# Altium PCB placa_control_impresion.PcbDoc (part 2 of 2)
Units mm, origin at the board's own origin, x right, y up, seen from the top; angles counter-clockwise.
Board outline 71.3 x 86.83 mm, 2 copper layers (Top Layer, Bottom Layer); 160 components, 36 nets, 619 pads, 364 vias.
Unrouted connection lines stored in the file: 1.
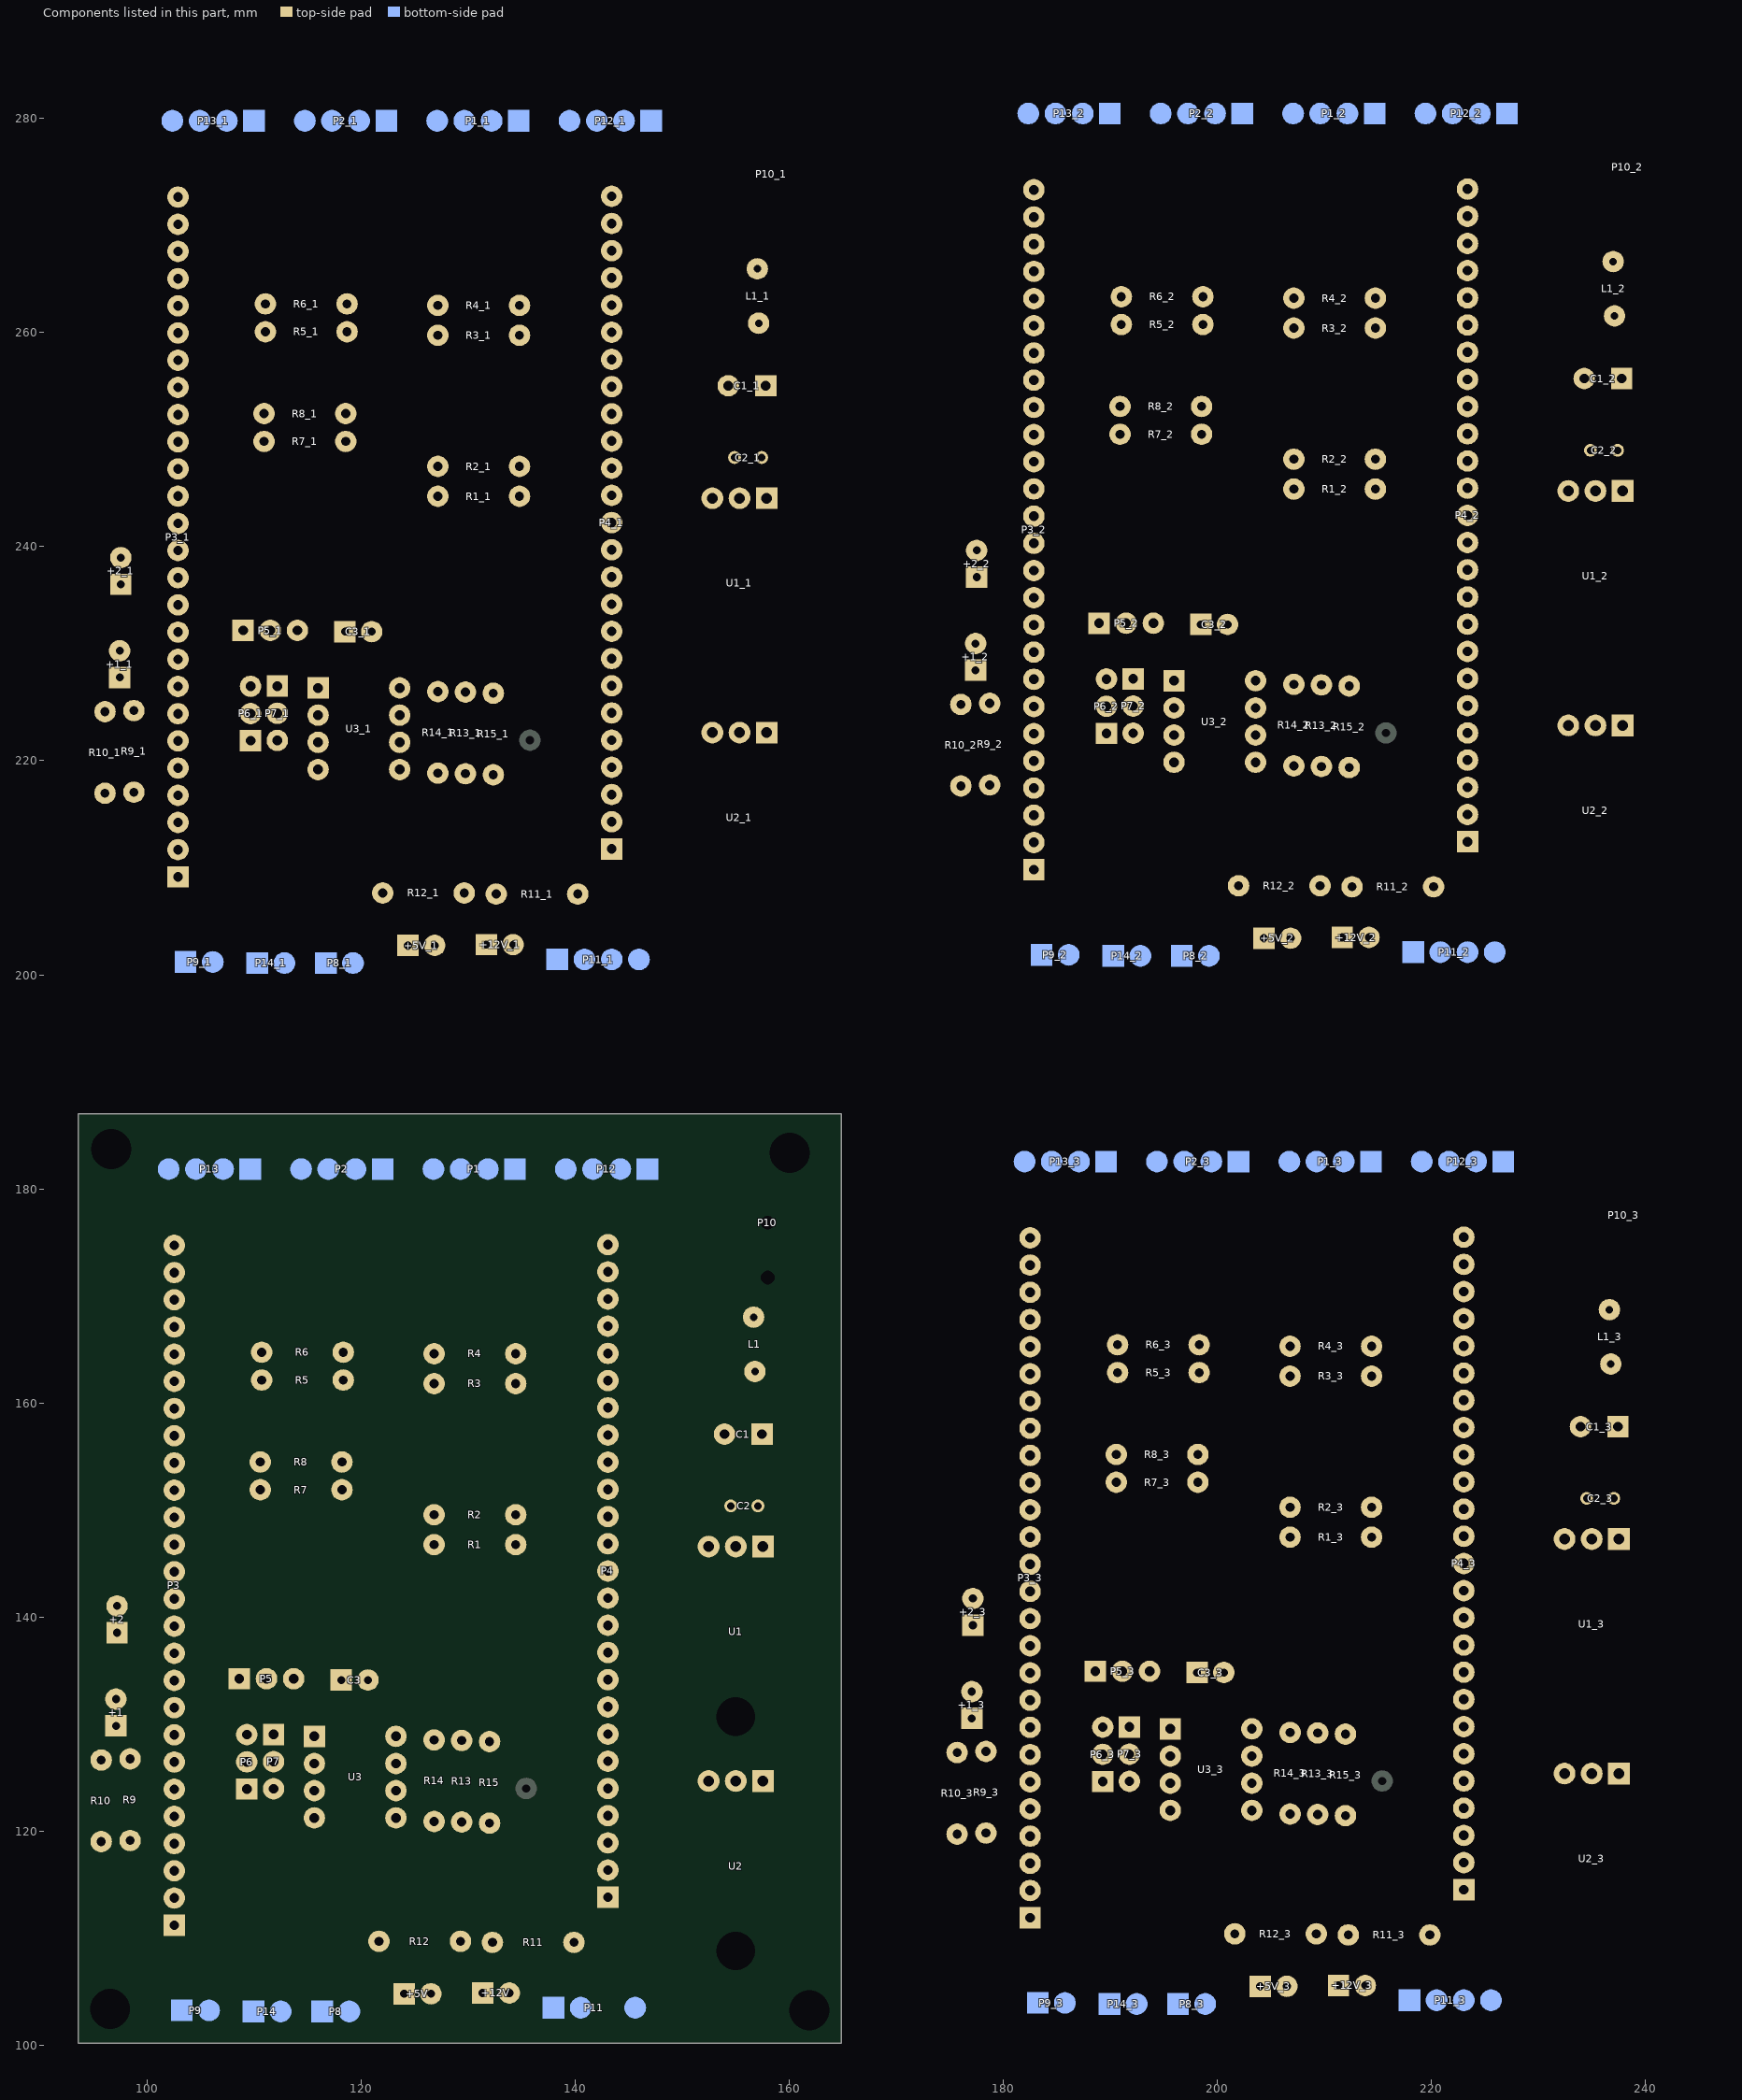
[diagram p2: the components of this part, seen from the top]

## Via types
v1: diameter 2, hole 0.711, Top Layer to Bottom Layer, 364 vias

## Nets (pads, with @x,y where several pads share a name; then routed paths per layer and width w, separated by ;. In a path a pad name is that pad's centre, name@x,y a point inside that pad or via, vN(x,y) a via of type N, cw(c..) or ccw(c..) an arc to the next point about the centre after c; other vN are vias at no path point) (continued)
pads on no net: +1_1.1 +1_1.2 +1_2.1 +1_2.2 +1_3.1 +1_3.2 +2_1.1 +2_1.2 +2_2.1 +2_2.2 +2_3.1 +2_3.2 +5V_1.1 +5V_1.2 +5V_2.1 +5V_2.2 +5V_3.1 +5V_3.2 +12V_1.1 +12V_1.2 +12V_2.1 +12V_2.2 +12V_3.1 +12V_3.2 C1_1.1 C1_1.2 C1_2.1 C1_2.2 C1_3.1 C1_3.2 C2_1.1 C2_1.2 C2_2.1 C2_2.2 C2_3.1 C2_3.2 C3_1.1 C3_1.2 C3_2.1 C3_2.2 C3_3.1 C3_3.2 L1_1.1 L1_1.2 L1_2.1 L1_2.2 L1_3.1 L1_3.2 P1_1.1 P1_1.2 P1_1.3 P1_1.4 P1_2.1 P1_2.2 P1_2.3 P1_2.4 P1_3.1 P1_3.2 P1_3.3 P1_3.4 P2_1.1 P2_1.2 P2_1.3 P2_1.4 P2_2.1 P2_2.2 P2_2.3 P2_2.4 P2_3.1 P2_3.2 P2_3.3 P2_3.4 P3.1 P3.3 P3.4 P3.5 P3.12 P3.13 P3.18 P3.19 P3.22 P3.23 P3.24 P3.25 P3.26 P3_1.1 P3_1.2 P3_1.3 P3_1.4 P3_1.5 P3_1.6 P3_1.7 P3_1.8 P3_1.9 P3_1.10 P3_1.11 P3_1.12 P3_1.13 P3_1.14 P3_1.15 P3_1.16 P3_1.17 P3_1.18 P3_1.19 P3_1.20 P3_1.21 P3_1.22 P3_1.23 P3_1.24 P3_1.25 P3_1.26 P3_2.1 P3_2.2 P3_2.3 P3_2.4 P3_2.5 P3_2.6 P3_2.7 P3_2.8 P3_2.9 P3_2.10 P3_2.11 P3_2.12 P3_2.13 P3_2.14 P3_2.15 P3_2.16 P3_2.17 P3_2.18 P3_2.19 P3_2.20 P3_2.21 P3_2.22 P3_2.23 P3_2.24 P3_2.25 P3_2.26 P3_3.1 P3_3.2 P3_3.3 P3_3.4 P3_3.5 P3_3.6 P3_3.7 P3_3.8 P3_3.9 P3_3.10 P3_3.11 P3_3.12 P3_3.13 P3_3.14 P3_3.15 P3_3.16 P3_3.17 P3_3.18 P3_3.19 P3_3.20 P3_3.21 P3_3.22 P3_3.23 P3_3.24 P3_3.25 P3_3.26 P4.3 P4.4 P4.6 P4.7 P4.8 P4.9 P4.10 P4.11 P4.12 P4.13 P4.17 P4.18 P4.19 P4.20 P4.22 P4.23 P4.24 P4.25 P4_1.1 P4_1.2 P4_1.3 P4_1.4 P4_1.5 P4_1.6 P4_1.7 P4_1.8 P4_1.9 P4_1.10 P4_1.11 P4_1.12 P4_1.13 P4_1.14 P4_1.15 P4_1.16 P4_1.17 P4_1.18 P4_1.19 P4_1.20 P4_1.21 P4_1.22 P4_1.23 P4_1.24 P4_1.25 P4_2.1 P4_2.2 P4_2.3 P4_2.4 P4_2.5 P4_2.6 P4_2.7 P4_2.8 P4_2.9 P4_2.10 P4_2.11 P4_2.12 P4_2.13 P4_2.14 P4_2.15 P4_2.16 P4_2.17 P4_2.18 P4_2.19 P4_2.20 P4_2.21 P4_2.22 P4_2.23 P4_2.24 P4_2.25 P4_3.1 P4_3.2 P4_3.3 P4_3.4 P4_3.5 P4_3.6 P4_3.7 P4_3.8 P4_3.9 P4_3.10 P4_3.11 P4_3.12 P4_3.13 P4_3.14 P4_3.15 P4_3.16 P4_3.17 P4_3.18 P4_3.19 P4_3.20 P4_3.21 P4_3.22 P4_3.23 P4_3.24 P4_3.25 P5_1.1 P5_1.2 P5_1.3 P5_2.1 P5_2.2 P5_2.3 P5_3.1 P5_3.2 P5_3.3 P6_1.1 P6_1.2 P6_1.3 P6_2.1 P6_2.2 P6_2.3 P6_3.1 P6_3.2 P6_3.3 P7_1.1 P7_1.2 P7_1.3 P7_2.1 P7_2.2 P7_2.3 P7_3.1 P7_3.2 P7_3.3 P8_1.1 P8_1.2 P8_2.1 P8_2.2 P8_3.1 P8_3.2 P9_1.1 P9_1.2 P9_2.1 P9_2.2 P9_3.1 P9_3.2 P10_1.2 P10_2.2 P10_3.2 P11_1.1 P11_1.2 P11_1.3 P11_1.4 P11_2.1 P11_2.2 P11_2.3 P11_2.4 P11_3.1 P11_3.2 P11_3.3 P11_3.4 P12_1.1 P12_1.2 P12_1.3 P12_1.4 P12_2.1 P12_2.2 P12_2.3 P12_2.4 P12_3.1 P12_3.2 P12_3.3 P12_3.4 P13_1.1 P13_1.2 P13_1.3 P13_1.4 P13_2.1 P13_2.2 P13_2.3 P13_2.4 P13_3.1 P13_3.2 P13_3.3 P13_3.4 P14_1.1 P14_1.2 P14_2.1 P14_2.2 P14_3.1 P14_3.2 R1_1.1 R1_1.2 R1_2.1 R1_2.2 R1_3.1 R1_3.2 R2_1.1 R2_1.2 R2_2.1 R2_2.2 R2_3.1 R2_3.2 R3_1.1 R3_1.2 R3_2.1 R3_2.2 R3_3.1 R3_3.2 R4_1.1 R4_1.2 R4_2.1 R4_2.2 R4_3.1 R4_3.2 R5_1.1 R5_1.2 R5_2.1 R5_2.2 R5_3.1 R5_3.2 R6_1.1 R6_1.2 R6_2.1 R6_2.2 R6_3.1 R6_3.2 R7_1.1 R7_1.2 R7_2.1 R7_2.2 R7_3.1 R7_3.2 R8_1.1 R8_1.2 R8_2.1 R8_2.2 R8_3.1 R8_3.2 R9_1.1 R9_1.2 R9_2.1 R9_2.2 R9_3.1 R9_3.2 R10_1.1 R10_1.2 R10_2.1 R10_2.2 R10_3.1 R10_3.2 R11_1.1 R11_1.2 R11_2.1 R11_2.2 R11_3.1 R11_3.2 R12_1.1 R12_1.2 R12_2.1 R12_2.2 R12_3.1 R12_3.2 R13_1.1 R13_1.2 R13_2.1 R13_2.2 R13_3.1 R13_3.2 R14_1.1 R14_1.2 R14_2.1 R14_2.2 R14_3.1 R14_3.2 R15_1.1 R15_1.2 R15_2.1 R15_2.2 R15_3.1 R15_3.2 U1_1.1 U1_1.2 U1_1.3 U1_1.4 U1_2.1 U1_2.2 U1_2.3 U1_2.4 U1_3.1 U1_3.2 U1_3.3 U1_3.4 U2_1.1 U2_1.2 U2_1.3 U2_1.4 U2_2.1 U2_2.2 U2_2.3 U2_2.4 U2_3.1 U2_3.2 U2_3.3 U2_3.4 U3_1.1 U3_1.2 U3_1.3 U3_1.4 U3_1.5 U3_1.6 U3_1.7 U3_1.8 U3_2.1 U3_2.2 U3_2.3 U3_2.4 U3_2.5 U3_2.6 U3_2.7 U3_2.8 U3_3.1 U3_3.2 U3_3.3 U3_3.4 U3_3.5 U3_3.6 U3_3.7 U3_3.8
copper on no net: | length 3961
  Bottom Layer w0.8: 95.975,224.55 95.975,225.1 95.55,225.525 95.55,231.425 97.55,233.425 97.55,236.475 ; 96.075,216.965 96.075,209.15 98.939,206.286 98.989,206.286 101.525,203.75 101.525,199.7 102.5,198.725 113.475,198.725 114.725,199.975 ; 97.25,238.975 98.225,238.975 102.575,234.625 ; 97.45,227.775 98.475,227.775 98.775,227.475 98.775,224.685 ; 97.45,230.275 97.45,230.525 99.01,232.085 v1@106.45,232.085 ; v1@98.9,164.64 v1@106.215,164.64 ; v1@98.94,116.38 v1@106.125,116.38 ; v1@98.94,154.48 v1@106.125,154.48 ; v1@98.94,157.02 v1@106.125,157.02 ; v1@98.94,167.18 v1@106.125,167.18 ; v1@98.94,169.72 v1@106.125,169.72 ; v1@98.94,172.26 v1@106.125,172.26 ; v1@98.94,174.8 v1@106.125,174.8 ; v1@99.01,111.23 v1@106.195,111.23 ; v1@99.15,260.025 111.055,260.025 111.065,260.015 111.065,262.675 ; v1@99.25,262.565 v1@106.565,262.565 ; v1@99.29,211.765 v1@106.475,211.765 ; v1@99.29,214.305 v1@106.475,214.305 ; v1(99.29,242.245) 107.355,242.245 108.975,240.625 108.975,232.175 ; v1(99.29,244.785) 107.74,244.785 111.515,241.01 111.515,232.175 ; v1(99.29,247.325) v1(106.475,247.325) ; v1@99.29,249.865 v1@106.475,249.865 ; v1@99.29,252.405 v1@106.475,252.405 ; v1@99.29,254.945 v1@106.475,254.945 ; v1@99.29,257.485 v1@106.475,257.485 ; v1@99.29,265.105 v1@106.475,265.105 ; v1@99.29,267.645 v1@106.475,267.645 ; v1@99.29,270.185 v1@106.475,270.185 ; v1@99.29,272.725 v1@106.475,272.725 ; v1@99.36,209.155 v1@106.545,209.155 ; 102.325,121.46 v1@106.125,121.46 ; 102.35,118.92 v1@106.125,118.92 ; 102.375,139.24 v1@106.125,139.24 ; 102.425,141.78 v1@106.125,141.78 ; 102.55,224.415 108.675,224.415 ; 102.675,219.385 v1@106.475,219.385 ; 102.7,216.845 v1@106.475,216.845 ; 102.725,237.165 v1@106.475,237.165 ; 102.775,239.705 v1@106.475,239.705 ; 102.8,221.925 109.625,221.925 109.675,221.875 ; 102.825,226.955 109.675,226.955 ; 102.825,229.545 108.02,229.545 108.85,230.375 114.85,230.375 116.025,231.55 116.025,245.325 114.45,246.9 114.45,270.05 109.995,274.505 109.995,279.78 ; 102.85,234.625 v1@106.475,234.625 ; 103.605,201.2 103.605,202.705 108.225,207.325 108.225,207.375 108.85,208 108.85,210.925 107.985,211.79 v1(106.45,211.79) ; 104.145,201.15 104.25,201.255 ; v1(106.45,249.89) 110.835,249.89 111,249.725 ; v1(106.45,257.51) 111.185,257.51 113.25,259.575 113.25,269.55 107.455,275.345 107.455,279.78 ; v1@106.5,247.425 109.1,247.425 114.055,242.47 114.055,232.175 ; 109.625,224.465 109.675,224.415 ; 110.94,249.825 110.94,252.425 ; 114.725,200 114.725,205.232 122.443,212.95 129.3,212.95 134.25,217.9 134.25,220.325 133.7,220.875 133.7,223.943 ; 114.742,279.78 114.742,274.358 115.65,273.45 115.65,251.175 117,249.825 118.56,249.825 ; 115.984,219.18 117.155,219.18 117.537,219.562 ; 115.984,221.72 116.06,221.795 116.06,224.29 116.1,224.25 ; 116.705,201.1 116.705,205.055 122.475,210.825 129.1,210.825 135.85,217.575 135.85,220.775 135.775,221.925 ; 117.282,279.78 117.282,274.359 116.85,273.927 116.85,261.91 118.685,260.075 ; 122.015,207.65 122.3,207.65 124.375,205.575 124.375,202.75 ; 127.075,279.025 127.075,270 129.075,268 129.075,261.2 127.618,259.743 127.174,259.743 ; 127.174,244.702 130.275,247.803 130.275,268.55 129.775,269.05 129.775,279.75 ; 131.725,203.025 131.725,207.49 ; 132.615,207.55 133.05,207.115 ; 134.644,260.325 134.669,260.35 ; 134.644,262.5 134.694,262.55 v1(139.6,262.55) ; 134.669,262.5 134.669,262.525 ; 134.725,244.8 134.755,244.77 v1(139.6,244.77) v1@139.532,244.702 ; 134.794,259.743 134.794,262.535 ; 134.825,244.825 134.825,247.675 ; v1@139.555,118.92 v1@146.74,118.92 ; v1@139.555,121.46 v1@146.74,121.46 ; v1@139.555,126.54 v1@146.74,126.54 ; v1@139.555,129.08 v1@146.74,129.08 ; v1@139.555,131.62 v1@146.74,131.62 ; v1@139.555,134.16 v1@146.74,134.16 ; v1@139.555,136.7 v1@146.74,136.7 ; v1@139.555,139.24 v1@146.74,139.24 ; v1@139.555,141.78 v1@146.74,141.78 ; v1@139.555,144.32 v1@146.74,144.32 ; v1@139.555,154.48 v1@146.74,154.48 ; v1@139.555,157.02 v1@146.74,157.02 ; v1@139.555,159.56 v1@146.74,159.56 ; v1@139.555,162.1 v1@146.74,162.1 ; v1@139.555,167.18 v1@146.74,167.18 ; v1@139.555,169.72 v1@146.74,169.72 ; v1@139.555,172.26 v1@146.74,172.26 ; v1@139.555,174.8 v1@146.74,174.8 ; v1(139.6,247.31) 137.64,247.31 136.41,248.54 136.41,253.39 132.75,257.05 132.75,270.5 137.7,275.45 143.075,275.45 144.555,276.93 144.555,279.78 ; v1@139.905,211.765 v1@147.09,211.765 ; v1@139.905,216.845 v1@147.09,216.845 ; v1@139.905,219.385 v1@147.09,219.385 ; v1@139.905,221.925 v1@147.09,221.925 ; v1@139.905,224.465 v1@147.09,224.465 ; v1@139.905,227.005 v1@147.09,227.005 ; v1@139.905,229.545 v1@147.09,229.545 ; v1@139.905,232.085 v1@147.09,232.085 ; v1@139.905,234.625 v1@147.09,234.625 ; v1@139.905,237.165 v1@147.09,237.165 ; v1@139.905,239.705 v1@147.09,239.705 ; v1@139.905,242.245 v1@147.09,242.245 ; v1@139.905,244.785 v1@147.09,244.785 ; v1@139.905,247.325 v1@147.09,247.325 ; v1@139.905,249.865 147.665,249.865 149.025,251.225 149.025,274.825 147.095,276.755 147.095,279.78 ; v1@139.905,252.405 v1@147.09,252.405 ; v1@139.905,254.945 v1@147.09,254.945 ; v1@139.905,257.485 v1@147.09,257.485 ; v1@139.905,260.025 v1@147.09,260.025 ; v1@139.905,262.565 v1@147.09,262.565 ; v1@139.905,265.105 v1@147.09,265.105 ; v1@139.905,267.645 v1@147.09,267.645 ; v1@139.905,270.185 v1@147.09,270.185 ; v1@139.905,272.725 v1@147.09,272.725 ; 140.235,207.55 136.3,203.615 136.3,200.125 137.55,198.875 144.775,198.875 145.95,200.05 145.95,201.445 ; 175.575,127.325 175.575,127.875 175.15,128.3 175.15,134.2 177.15,136.2 177.15,139.25 ; 175.675,119.74 175.675,111.925 178.539,109.061 178.589,109.061 181.125,106.525 181.125,102.475 182.1,101.5 193.075,101.5 194.325,102.75 ; 175.925,225.225 175.925,225.775 175.5,226.2 175.5,232.1 177.5,234.1 177.5,237.15 ; 176.025,217.64 176.025,209.825 178.889,206.961 178.939,206.961 181.475,204.425 181.475,200.375 182.45,199.4 193.425,199.4 194.675,200.65 ; 176.85,141.75 177.825,141.75 182.175,137.4 ; 177.05,130.55 178.075,130.55 178.375,130.25 178.375,127.46 ; 177.05,133.05 177.05,133.3 178.61,134.86 v1@186.05,134.86 ; 177.2,239.65 178.175,239.65 182.525,235.3 ; 177.4,228.45 178.425,228.45 178.725,228.15 178.725,225.36 ; 177.4,230.95 177.4,231.2 178.96,232.76 v1@186.4,232.76 ; v1@178.75,162.8 190.655,162.8 190.665,162.79 190.665,165.45 ; v1@178.85,165.34 v1@186.165,165.34 ; v1@178.89,114.54 v1@186.075,114.54 ; v1@178.89,117.08 v1@186.075,117.08 ; v1(178.89,145.02) 186.955,145.02 188.575,143.4 188.575,134.95 ; v1(178.89,147.56) 187.34,147.56 191.115,143.785 191.115,134.95 ; v1(178.89,150.1) v1(186.075,150.1) ; v1@178.89,152.64 v1@186.075,152.64 ; v1@178.89,155.18 v1@186.075,155.18 ; v1@178.89,157.72 v1@186.075,157.72 ; v1@178.89,160.26 v1@186.075,160.26 ; v1@178.89,167.88 v1@186.075,167.88 ; v1@178.89,170.42 v1@186.075,170.42 ; v1@178.89,172.96 v1@186.075,172.96 ; v1@178.89,175.5 v1@186.075,175.5 ; v1@178.96,111.93 v1@186.145,111.93 ; v1@179.1,260.7 191.005,260.7 191.015,260.69 191.015,263.35 ; v1@179.2,263.24 v1@186.515,263.24 ; v1@179.24,212.44 v1@186.425,212.44 ; v1@179.24,214.98 v1@186.425,214.98 ; v1(179.24,242.92) 187.305,242.92 188.925,241.3 188.925,232.85 ; v1(179.24,245.46) 187.69,245.46 191.465,241.685 191.465,232.85 ; v1(179.24,248) v1(186.425,248) ; v1@179.24,250.54 v1@186.425,250.54 ; v1@179.24,253.08 v1@186.425,253.08 ; v1@179.24,255.62 v1@186.425,255.62 ; v1@179.24,258.16 v1@186.425,258.16 ; v1@179.24,265.78 v1@186.425,265.78 ; v1@179.24,268.32 v1@186.425,268.32 ; v1@179.24,270.86 v1@186.425,270.86 ; v1@179.24,273.4 v1@186.425,273.4 ; v1@179.31,209.83 v1@186.495,209.83 ; 182.15,127.19 188.275,127.19 ; 182.275,122.16 v1@186.075,122.16 ; 182.3,119.62 v1@186.075,119.62 ; 182.325,139.94 v1@186.075,139.94 ; 182.375,142.48 v1@186.075,142.48 ; 182.4,124.7 189.225,124.7 189.275,124.65 ; 182.425,129.73 189.275,129.73 ; 182.425,132.32 187.62,132.32 188.45,133.15 194.45,133.15 195.625,134.325 195.625,148.1 194.05,149.675 194.05,172.825 189.595,177.28 189.595,182.555 ; 182.45,137.4 v1@186.075,137.4 ; 182.5,225.09 188.625,225.09 ; 182.625,220.06 v1@186.425,220.06 ; 182.65,217.52 v1@186.425,217.52 ; 182.675,237.84 v1@186.425,237.84 ; 182.725,240.38 v1@186.425,240.38 ; 182.75,222.6 189.575,222.6 189.625,222.55 ; 182.775,227.63 189.625,227.63 ; 182.775,230.22 187.97,230.22 188.8,231.05 194.8,231.05 195.975,232.225 195.975,246 194.4,247.575 194.4,270.725 189.945,275.18 189.945,280.455 ; 182.8,235.3 v1@186.425,235.3 ; 183.205,103.975 183.205,105.48 187.825,110.1 187.825,110.15 188.45,110.775 188.45,113.7 187.585,114.565 v1(186.05,114.565) ; 183.555,201.875 183.555,203.38 188.175,208 188.175,208.05 188.8,208.675 188.8,211.6 187.935,212.465 v1(186.4,212.465) ; 183.745,103.925 183.85,104.03 ; 184.095,201.825 184.2,201.93 ; v1(186.05,152.665) 190.435,152.665 190.6,152.5 ; v1(186.05,160.285) 190.785,160.285 192.85,162.35 192.85,172.325 187.055,178.12 187.055,182.555 ; v1@186.1,150.2 188.7,150.2 193.655,145.245 193.655,134.95 ; v1(186.4,250.565) 190.785,250.565 190.95,250.4 ; v1(186.4,258.185) 191.135,258.185 193.2,260.25 193.2,270.225 187.405,276.02 187.405,280.455 ; v1@186.45,248.1 189.05,248.1 194.005,243.145 194.005,232.85 ; 189.225,127.24 189.275,127.19 ; 189.575,225.14 189.625,225.09 ; 190.54,152.6 190.54,155.2 ; 190.89,250.5 190.89,253.1 ; 194.325,102.775 194.325,108.007 202.043,115.725 208.9,115.725 213.85,120.675 213.85,123.1 213.3,123.65 213.3,126.718 ; 194.342,182.555 194.342,177.133 195.25,176.225 195.25,153.95 196.6,152.6 198.16,152.6 ; 194.675,200.675 194.675,205.907 202.393,213.625 209.25,213.625 214.2,218.575 214.2,221 213.65,221.55 213.65,224.618 ; 194.692,280.455 194.692,275.033 195.6,274.125 195.6,251.85 196.95,250.5 198.51,250.5 ; 195.584,121.955 196.755,121.955 197.137,122.337 ; 195.584,124.495 195.66,124.57 195.66,127.065 195.7,127.025 ; 195.934,219.855 197.105,219.855 197.487,220.237 ; 195.934,222.395 196.01,222.47 196.01,224.965 196.05,224.925 ; 196.305,103.875 196.305,107.83 202.075,113.6 208.7,113.6 215.45,120.35 215.45,123.55 215.375,124.7 ; 196.655,201.775 196.655,205.73 202.425,211.5 209.05,211.5 215.8,218.25 215.8,221.45 215.725,222.6 ; 196.882,182.555 196.882,177.134 196.45,176.702 196.45,164.685 198.285,162.85 ; 197.232,280.455 197.232,275.034 196.8,274.602 196.8,262.585 198.635,260.75 ; 201.615,110.425 201.9,110.425 203.975,108.35 203.975,105.525 ; 201.965,208.325 202.25,208.325 204.325,206.25 204.325,203.425 ; 206.675,181.8 206.675,172.775 208.675,170.775 208.675,163.975 207.218,162.518 206.774,162.518 ; 206.774,147.477 209.875,150.578 209.875,171.325 209.375,171.825 209.375,182.525 ; 207.025,279.7 207.025,270.675 209.025,268.675 209.025,261.875 207.568,260.418 207.124,260.418 ; 207.124,245.377 210.225,248.478 210.225,269.225 209.725,269.725 209.725,280.425 ; 211.325,105.8 211.325,110.265 ; 211.675,203.7 211.675,208.165 ; 212.215,110.325 212.65,109.89 ; 212.565,208.225 213,207.79 ; 214.244,163.1 214.269,163.125 ; 214.244,165.275 214.294,165.325 v1(219.2,165.325) ; 214.269,165.275 214.269,165.3 ; 214.325,147.575 214.355,147.545 v1(219.2,147.545) v1@219.132,147.477 ; 214.394,162.518 214.394,165.31 ; 214.425,147.6 214.425,150.45 ; 214.594,261 214.619,261.025 ; 214.594,263.175 214.644,263.225 v1(219.55,263.225) ; 214.619,263.175 214.619,263.2 ; 214.675,245.475 214.705,245.445 v1(219.55,245.445) v1@219.482,245.377 ; 214.744,260.418 214.744,263.21 ; 214.775,245.5 214.775,248.35 ; v1(219.2,150.085) 217.24,150.085 216.01,151.315 216.01,156.165 212.35,159.825 212.35,173.275 217.3,178.225 222.675,178.225 224.155,179.705 224.155,182.555 ; v1@219.505,114.54 v1@226.69,114.54 ; v1@219.505,119.62 v1@226.69,119.62 ; v1@219.505,122.16 v1@226.69,122.16 ; v1@219.505,124.7 v1@226.69,124.7 ; v1@219.505,127.24 v1@226.69,127.24 ; v1@219.505,129.78 v1@226.69,129.78 ; v1@219.505,132.32 v1@226.69,132.32 ; v1@219.505,134.86 v1@226.69,134.86 ; v1@219.505,137.4 v1@226.69,137.4 ; v1@219.505,139.94 v1@226.69,139.94 ; v1@219.505,142.48 v1@226.69,142.48 ; v1@219.505,145.02 v1@226.69,145.02 ; v1@219.505,147.56 v1@226.69,147.56 ; v1@219.505,152.64 227.265,152.64 228.625,154 228.625,177.6 226.695,179.53 226.695,182.555 ; v1@219.505,157.72 v1@226.69,157.72 ; v1@219.505,160.26 v1@226.69,160.26 ; v1@219.505,162.8 v1@226.69,162.8 ; v1@219.505,167.88 v1@226.69,167.88 ; v1@219.505,170.42 v1@226.69,170.42 ; v1@219.505,172.96 v1@226.69,172.96 ; v1@219.505,175.5 v1@226.69,175.5 ; v1@219.505,150.1 v1@226.69,150.1 ; v1@219.505,155.18 v1@226.69,155.18 ; v1@219.505,165.34 v1@226.69,165.34 ; v1(219.55,247.985) 217.59,247.985 216.36,249.215 216.36,254.065 212.7,257.725 212.7,271.175 217.65,276.125 223.025,276.125 224.505,277.605 224.505,280.455 ; 219.835,110.325 215.9,106.39 215.9,102.9 217.15,101.65 224.375,101.65 225.55,102.825 225.55,104.22 ; v1@219.855,212.44 v1@227.04,212.44 ; v1@219.855,217.52 v1@227.04,217.52 ; v1@219.855,220.06 v1@227.04,220.06 ; v1@219.855,222.6 v1@227.04,222.6 ; v1@219.855,225.14 v1@227.04,225.14 ; v1@219.855,227.68 v1@227.04,227.68 ; v1@219.855,230.22 v1@227.04,230.22 ; v1@219.855,232.76 v1@227.04,232.76 ; v1@219.855,235.3 v1@227.04,235.3 ; v1@219.855,237.84 v1@227.04,237.84 ; v1@219.855,240.38 v1@227.04,240.38 ; v1@219.855,242.92 v1@227.04,242.92 ; v1@219.855,245.46 v1@227.04,245.46 ; v1@219.855,248 v1@227.04,248 ; v1@219.855,250.54 227.615,250.54 228.975,251.9 228.975,275.5 227.045,277.43 227.045,280.455 ; v1@219.855,253.08 v1@227.04,253.08 ; v1@219.855,255.62 v1@227.04,255.62 ; v1@219.855,258.16 v1@227.04,258.16 ; v1@219.855,260.7 v1@227.04,260.7 ; v1@219.855,263.24 v1@227.04,263.24 ; v1@219.855,265.78 v1@227.04,265.78 ; v1@219.855,268.32 v1@227.04,268.32 ; v1@219.855,270.86 v1@227.04,270.86 ; v1@219.855,273.4 v1@227.04,273.4 ; 220.185,208.225 216.25,204.29 216.25,200.8 217.5,199.55 224.725,199.55 225.9,200.725 225.9,202.12
  Bottom Layer w1: 96.075,216.965 96.135,217.025 98.875,217.025 ; 110.305,201.1 110.305,204.73 113.075,207.5 ; 112.175,221.895 115.809,221.895 115.984,221.72 ; 112.175,224.435 113.11,224.435 115.5,226.825 ; 112.175,226.975 112.175,227.75 113.275,228.85 117.675,228.85 118.675,227.85 118.675,220.7 117.537,219.562 ; 112.775,224.725 112.875,224.725 ; 112.845,201.1 112.845,205.19 122.28,214.625 128.285,214.625 132.35,218.69 ; 113.125,207.45 121.7,216.025 ; 115.4,226.825 116.125,226.825 ; 115.965,222.195 116.06,222.1 ; 120.979,215.304 121.825,216.15 127.2,216.15 129.95,218.9 ; 121.492,232.058 123.604,229.946 123.604,226.8 ; 123.604,224.26 128.215,224.26 ; 123.604,229.2 127.825,229.2 129.75,227.275 ; 124.296,221.72 126.916,219.1 ; 127.176,218.84 127.176,219.226 ; 127.216,226.5 127.176,226.46 127.176,224.649 127.826,224.649 132.35,220.125 132.35,218.7 132.345,218.695 ; 127.3,218.875 127.354,218.821 129.871,218.821 ; 129.635,208.36 135.58,214.305 143.405,214.305 143.41,214.3 v1@146.675,214.3 ; 129.7,218.84 129.75,218.79 ; 129.75,225.5 129.75,225.75 131.557,223.943 136.607,223.943 137.7,222.85 137.7,214.305 ; 137.83,214.305 138,214.475 ; 140.87,201.445 140.87,201.92 147.237,208.287 149.445,210.495 149.445,221.02 151.05,222.625 152.81,222.625 ; 147.095,279.78 147.645,279.78 ; v1(147.325,214.35) 149.125,214.35 ; 175.675,119.74 175.735,119.8 178.475,119.8 ; 176.025,217.64 176.085,217.7 178.825,217.7 ; 189.905,103.875 189.905,107.505 192.675,110.275 ; 190.255,201.775 190.255,205.405 193.025,208.175 ; 191.775,124.67 195.409,124.67 195.584,124.495 ; 191.775,127.21 192.71,127.21 195.1,129.6 ; 191.775,129.75 191.775,130.525 192.875,131.625 197.275,131.625 198.275,130.625 198.275,123.475 197.137,122.337 ; 192.125,222.57 195.759,222.57 195.934,222.395 ; 192.125,225.11 193.06,225.11 195.45,227.5 ; 192.125,227.65 192.125,228.425 193.225,229.525 197.625,229.525 198.625,228.525 198.625,221.375 197.487,220.237 ; 192.375,127.5 192.475,127.5 ; 192.445,103.875 192.445,107.965 201.88,117.4 207.885,117.4 211.95,121.465 ; 192.725,110.225 201.3,118.8 ; 192.725,225.4 192.825,225.4 ; 192.795,201.775 192.795,205.865 202.23,215.3 208.235,215.3 212.3,219.365 ; 193.075,208.125 201.65,216.7 ; 195,129.6 195.725,129.6 ; 195.35,227.5 196.075,227.5 ; 195.565,124.97 195.66,124.875 ; 195.915,222.87 196.01,222.775 ; 200.579,118.079 201.425,118.925 206.8,118.925 209.55,121.675 ; 200.929,215.979 201.775,216.825 207.15,216.825 209.9,219.575 ; 201.092,134.833 203.204,132.721 203.204,129.575 ; 201.442,232.733 203.554,230.621 203.554,227.475 ; 203.204,127.035 207.815,127.035 ; 203.204,131.975 207.425,131.975 209.35,130.05 ; 203.554,224.935 208.165,224.935 ; 203.554,229.875 207.775,229.875 209.7,227.95 ; 203.896,124.495 206.516,121.875 ; 204.246,222.395 206.866,219.775 ; 206.776,121.615 206.776,122.001 ; 206.816,129.275 206.776,129.235 206.776,127.424 207.426,127.424 211.95,122.9 211.95,121.475 211.945,121.47 ; 206.9,121.65 206.954,121.596 209.471,121.596 ; 207.126,219.515 207.126,219.901 ; 207.166,227.175 207.126,227.135 207.126,225.324 207.776,225.324 212.3,220.8 212.3,219.375 212.295,219.37 ; 207.25,219.55 207.304,219.496 209.821,219.496 ; 209.235,111.135 215.18,117.08 223.005,117.08 223.01,117.075 v1@226.275,117.075 ; 209.3,121.615 209.35,121.565 ; 209.35,128.275 209.35,128.525 211.157,126.718 216.207,126.718 217.3,125.625 217.3,117.08 ; 209.585,209.035 215.53,214.98 223.355,214.98 223.36,214.975 v1@226.625,214.975 ; 209.65,219.515 209.7,219.465 ; 209.7,226.175 209.7,226.425 211.507,224.618 216.557,224.618 217.65,223.525 217.65,214.98 ; 217.43,117.08 217.6,117.25 ; 217.78,214.98 217.95,215.15 ; 220.47,104.22 220.47,104.695 226.837,111.062 229.045,113.27 229.045,123.795 230.65,125.4 232.41,125.4 ; 220.82,202.12 220.82,202.595 227.187,208.962 229.395,211.17 229.395,221.695 231,223.3 232.76,223.3 ; 226.695,182.555 227.245,182.555 ; v1(226.925,117.125) 228.725,117.125 ; 227.045,280.455 227.595,280.455 ; v1(227.275,215.025) 229.075,215.025
  Bottom Layer w1.5: 102.375,279.78 102.375,281.2 104.25,283.075 149.5,283.075 152.125,280.45 152.125,245.21 152.875,244.46 152.875,239.3 158.09,234.085 ; 122.362,279.78 122.362,282.562 122.375,282.575 ; 134.728,279.78 134.728,282.528 134.775,282.575 ; 139.475,279.78 139.475,282.5 139.55,282.575 ; 145.95,201.445 145.95,202.275 147.667,203.992 147.667,204.042 157.89,214.265 157.89,223.54 160.65,226.3 160.65,231.625 154.775,237.5 ; 157.01,265.952 160.727,265.952 161.825,267.05 161.825,273.95 160.95,274.825 158.425,274.825 ; 157.137,260.072 157.137,259.163 157.99,258.31 157.99,244.525 ; 181.975,182.555 181.975,183.975 183.85,185.85 229.1,185.85 231.725,183.225 231.725,147.985 232.475,147.235 232.475,142.075 237.69,136.86 ; 182.325,280.455 182.325,281.875 184.2,283.75 229.45,283.75 232.075,281.125 232.075,245.885 232.825,245.135 232.825,239.975 238.04,234.76 ; 201.962,182.555 201.962,185.337 201.975,185.35 ; 202.312,280.455 202.312,283.237 202.325,283.25 ; 214.328,182.555 214.328,185.303 214.375,185.35 ; 214.678,280.455 214.678,283.203 214.725,283.25 ; 219.075,182.555 219.075,185.275 219.15,185.35 ; 219.425,280.455 219.425,283.175 219.5,283.25 ; 225.55,104.22 225.55,105.05 227.267,106.767 227.267,106.817 237.49,117.04 237.49,126.315 240.25,129.075 240.25,134.4 234.375,140.275 ; 225.9,202.12 225.9,202.95 227.617,204.667 227.617,204.717 237.84,214.94 237.84,224.215 240.6,226.975 240.6,232.3 234.725,238.175 ; 236.61,168.727 240.327,168.727 241.425,169.825 241.425,176.725 240.55,177.6 238.025,177.6 ; 236.737,162.847 236.737,161.938 237.59,161.085 237.59,147.3 ; 236.96,266.627 240.677,266.627 241.775,267.725 241.775,274.625 240.9,275.5 238.375,275.5 ; 237.087,260.747 237.087,259.838 237.94,258.985 237.94,245.2
  other v1: 98.97,111.24 106.17,111.255 178.92,111.94 186.12,111.955 219.2,114.525 178.85,114.55 226.825,114.545 98.9,116.39 106.1,116.405 178.85,117.09 186.05,117.105 139.25,118.905 146.875,118.925 106.1,118.945 219.2,119.605 186.05,119.645 226.825,119.625 139.25,121.445 146.875,121.465 106.1,121.485 219.2,122.145 186.05,122.185 226.825,122.165 219.2,124.685 186.05,124.725 226.825,124.705 139.25,126.525 146.875,126.545 219.2,127.225 186.05,127.265 226.825,127.245 139.25,129.065 146.875,129.085 219.2,129.765 186.05,129.805 226.825,129.785 139.25,131.605 146.875,131.625 186.05,132.32 219.2,132.305 226.825,132.325 139.25,134.145 146.875,134.165 219.2,134.845 186.05,134.885 226.825,134.865 139.25,136.685 146.875,136.705 219.2,137.385 186.05,137.425 226.825,137.405 139.25,139.225 146.875,139.245 106.1,139.265 219.2,139.925 186.05,139.965 226.825,139.945 139.25,141.765 146.875,141.785 106.1,141.805 219.2,142.465 186.05,142.505 226.825,142.485 139.25,144.305 146.875,144.325 186.075,145.02 219.2,145.005 226.825,145.025 186.075,147.56 226.825,147.565 226.825,150.105 219.2,152.625 226.8,152.64 178.85,152.65 139.25,154.465 98.9,154.49 146.875,154.485 106.1,154.505 219.2,155.165 178.85,155.19 186.05,155.205 226.825,155.185 139.25,157.005 98.9,157.03 146.875,157.025 106.1,157.045 219.2,157.705 178.85,157.73 186.05,157.745 226.825,157.725 139.25,159.545 146.875,159.565 219.2,160.245 178.85,160.27 226.825,160.265 139.25,162.085 146.875,162.105 219.2,162.785 178.85,162.81 186.05,162.825 226.825,162.805 98.9,164.65 106.1,164.665 178.85,165.35 186.05,165.365 226.825,165.345 139.25,167.165 98.9,167.19 146.875,167.185 106.1,167.205 219.2,167.865 178.85,167.89 186.05,167.905 226.825,167.885 139.25,169.705 98.9,169.73 146.875,169.725 106.1,169.745 219.2,170.405 178.85,170.43 186.05,170.445 226.825,170.425 139.25,172.245 98.9,172.27 146.875,172.265 106.1,172.285 219.2,172.945 178.85,172.97 186.05,172.985 226.825,172.965 139.25,174.785 98.9,174.81 146.875,174.805 106.1,174.825 219.2,175.485 178.85,175.51 186.05,175.525 226.825,175.505 99.32,209.165 106.52,209.18 179.27,209.84 186.47,209.855 139.6,211.75 147.225,211.77 99.25,211.775 219.55,212.425 179.2,212.45 227.175,212.445 99.25,214.315 106.45,214.33 179.2,214.99 186.4,215.005 139.6,216.83 147.225,216.85 106.45,216.87 219.55,217.505 227.175,217.525 186.4,217.545 139.6,219.37 147.225,219.39 106.45,219.41 219.55,220.045 227.175,220.065 186.4,220.085 139.6,221.91 147.225,221.93 106.45,221.95 219.55,222.585 227.175,222.605 186.4,222.625 139.6,224.45 147.225,224.47 106.45,224.49 219.55,225.125 227.175,225.145 186.4,225.165 139.6,226.99 147.225,227.01 106.45,227.03 219.55,227.665 227.175,227.685 186.4,227.705 106.45,229.545 139.6,229.53 147.225,229.55 219.55,230.205 186.4,230.22 227.175,230.225 139.6,232.07 147.225,232.09 106.45,232.11 219.55,232.745 227.175,232.765 186.4,232.785 139.6,234.61 147.225,234.63 106.45,234.65 219.55,235.285 227.175,235.305 186.4,235.325 139.6,237.15 147.225,237.17 106.45,237.19 219.55,237.825 227.175,237.845 186.4,237.865 139.6,239.69 147.225,239.71 106.45,239.73 219.55,240.365 227.175,240.385 186.4,240.405 106.475,242.245 139.6,242.23 147.225,242.25 219.55,242.905 186.425,242.92 227.175,242.925 106.475,244.785 147.225,244.79 186.425,245.46 227.175,245.465 147.225,247.33 227.175,248.005 139.6,249.85 147.2,249.865 99.25,249.875 219.55,250.525 179.2,250.55 227.15,250.54 139.6,252.39 147.225,252.41 99.25,252.415 106.45,252.43 219.55,253.065 179.2,253.09 227.175,253.085 186.4,253.105 139.6,254.93 147.225,254.95 99.25,254.955 106.45,254.97 219.55,255.605 179.2,255.63 227.175,255.625 186.4,255.645 139.6,257.47 147.225,257.49 99.25,257.495 219.55,258.145 179.2,258.17 227.175,258.165 139.6,260.01 147.225,260.03 99.25,260.035 106.45,260.05 219.55,260.685 179.2,260.71 227.175,260.705 186.4,260.725 147.225,262.57 99.25,262.575 106.45,262.59 179.2,263.25 227.175,263.245 186.4,263.265 139.6,265.09 147.225,265.11 99.25,265.115 106.45,265.13 219.55,265.765 179.2,265.79 227.175,265.785 186.4,265.805 139.6,267.63 147.225,267.65 99.25,267.655 106.45,267.67 219.55,268.305 179.2,268.33 227.175,268.325 186.4,268.345 139.6,270.17 147.225,270.19 99.25,270.195 106.45,270.21 219.55,270.845 179.2,270.87 227.175,270.865 186.4,270.885 139.6,272.71 147.225,272.73 99.25,272.735 106.45,272.75 219.55,273.385 179.2,273.41 227.175,273.405 186.4,273.425

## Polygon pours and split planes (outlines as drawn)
no net on Bottom Layer "plano_señal_fuerte" (solid, remove dead copper, pour order 1000): 173.55,187.739 173.612,187.775 244.85,187.775 244.819,187.757 244.819,100.993 244.85,100.975 173.706,100.975 173.612,101.03 173.55,101.066
no net on Bottom Layer "plano_señal_fuerte" (solid, remove dead copper, pour order 1000): 173.9,285.639 173.962,285.675 245.2,285.675 245.169,285.657 245.169,198.893 245.2,198.875 174.056,198.875 173.962,198.93 173.9,198.966
no net on Bottom Layer "plano_señal_fuerte" (solid, remove dead copper, pour order 1000): 93.95,284.964 94.012,285 165.25,285 165.219,284.982 165.219,198.218 165.25,198.2 94.106,198.2 94.012,198.255 93.95,198.291
GND on Bottom Layer "plano_señal_fuerte" (solid, remove dead copper, pour order 1000): 93.6,187.039 93.662,187.075 164.9,187.075 164.869,187.057 164.869,100.293 164.9,100.275 93.756,100.275 93.662,100.33 93.6,100.366

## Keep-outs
Drill Guide:
  rectangle: 180.25,107.225 225.65,177.425
  rectangle: 180.6,205.125 226,275.325
  rectangle: 100.65,204.45 146.05,274.65
  rectangle: 100.3,106.525 145.7,176.725

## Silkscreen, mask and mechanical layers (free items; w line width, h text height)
Top Overlay:
  lines w0.254: 135.425,124.025 139.21,124.025 139.25,123.985 ; 135.775,221.95 139.56,221.95 139.6,221.91 ; 215.375,124.725 219.16,124.725 219.2,124.685 ; 215.725,222.625 219.51,222.625 219.55,222.585
Drill Drawing:
  lines w0.254: 93.425,72.425 93.475,72.475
